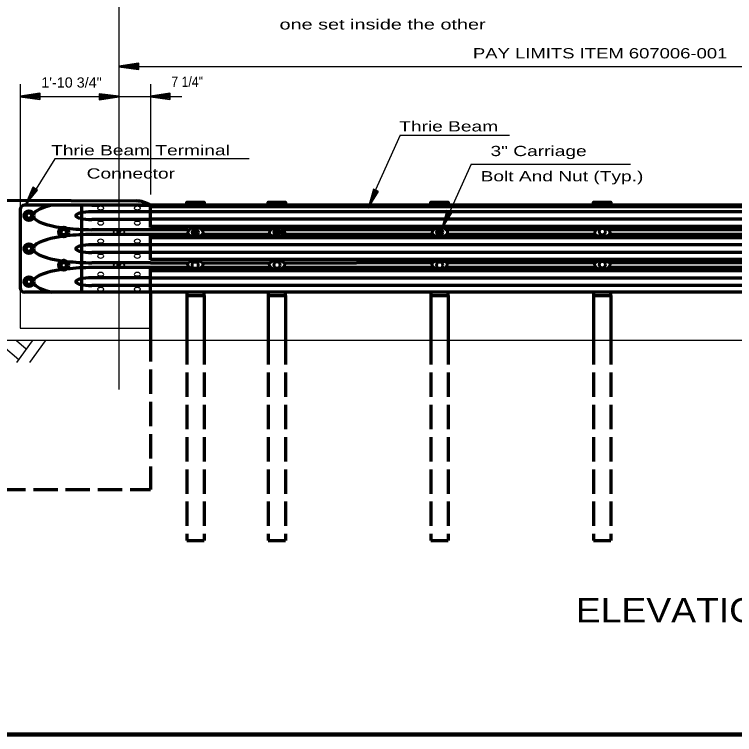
# Model space of a CAD drawing. Extents: x 856.9 to 891.7, y -2278.5 to -2254.7.
# Drawn here: x 863.91 to 872.97, y -2277.16 to -2268.1 of the extents above; entities that cross this region are included whole.
import ezdxf
from ezdxf.enums import TextEntityAlignment as Align

# ---------------------------------------------------------------- set-up
doc = ezdxf.new("R2010")
doc.units = 0
doc.header["$LTSCALE"] = 0.051
doc.header["$PDMODE"] = 32
doc.header["$PDSIZE"] = 0.0255
doc.linetypes.add('LONG_DASHED', pattern=[7.5, 6, -1.5])
doc.layers.add('1', color=7, linetype='Continuous', lineweight=70)
doc.layers.add('3', color=7, linetype='Continuous', lineweight=40)

msp = doc.modelspace()

# ---------------------------------------------------------------- linework, layer by layer
at = {"layer": '1', "lineweight": 25}
for p, q in [((865.22225, -2263.57275), (865.22225, -2272.82167)), ((865.22225, -2268.76158), (877.53042, -2268.76158)), ((863.98108, -2268.98175), (863.98108, -2270.37008)), ((865.61775, -2268.98175), (865.61775, -2270.37008)), ((868.75875, -2269.62258), (868.39367, -2270.431)), ((868.75925, -2269.62283), (870.134, -2269.62283)), ((864.41333, -2269.9225), (864.05383, -2270.50192)), ((866.86067, -2269.9225), (864.41333, -2269.9225)), ((869.651, -2269.98842), (869.28542, -2270.798)), ((869.651, -2269.98842), (871.65808, -2269.98842)), ((862.12625, -2272.20317), (882.07667, -2272.20317)), ((864.05633, -2272.31575), (863.93258, -2272.20975)), ((863.93525, -2272.48467), (864.133, -2272.20975)), ((864.09892, -2272.48467), (864.29667, -2272.20975)), ((863.96075, -2272.44933), (863.76567, -2272.28183))]:
    msp.add_line(p, q, dxfattribs=at)
at = {"layer": '1'}
for p, q in [((863.80467, -2270.44258), (865.43792, -2270.45175)), ((865.61775, -2270.5055), (864.03542, -2270.5055)), ((864.74875, -2270.50742), (864.74875, -2271.59408)), ((873.7235, -2270.5055), (865.61775, -2270.5055)), ((863.98108, -2270.5605), (863.98108, -2271.54242)), ((865.61775, -2270.58667), (864.881, -2270.58667)), ((865.61775, -2270.51925), (873.7235, -2270.51925)), ((873.7235, -2270.58867), (865.61775, -2270.58867)), ((865.61775, -2270.68367), (864.881, -2270.68367)), ((867.41158, -2270.68233), (865.61775, -2270.68233)), ((873.7235, -2270.68233), (867.41158, -2270.68233)), ((867.41158, -2270.77067), (865.61775, -2270.77067)), ((873.7235, -2270.77067), (867.41158, -2270.77067)), ((865.61775, -2270.81267), (864.881, -2270.81267)), ((865.61775, -2270.87425), (864.881, -2270.87425)), ((866.096, -2270.81267), (865.61775, -2270.81267)), ((866.09517, -2270.8735), (865.62342, -2270.8735)), ((867.129, -2270.81267), (866.27008, -2270.81267)), ((867.12075, -2270.8735), (866.27708, -2270.8735)), ((868.21067, -2270.81267), (867.29283, -2270.81267)), ((868.21067, -2270.8735), (867.29925, -2270.8735)), ((869.17425, -2270.81267), (868.21067, -2270.81267)), ((869.17425, -2270.8735), (868.21067, -2270.8735)), ((873.32717, -2270.81267), (871.38492, -2270.81267)), ((873.32717, -2270.8735), (871.38492, -2270.8735)), ((873.7235, -2270.91617), (865.61775, -2270.91617)), ((865.61775, -2271.00258), (864.881, -2271.00258)), ((873.7235, -2271.004), (865.61775, -2271.004)), ((865.61775, -2271.09958), (864.881, -2271.09958)), ((873.73325, -2271.09817), (865.61775, -2271.09817)), ((865.61775, -2271.22833), (864.881, -2271.22833)), ((873.7235, -2271.18667), (865.61775, -2271.18667)), ((865.61775, -2271.22833), (866.08875, -2271.22833)), ((866.27533, -2271.22833), (867.11167, -2271.22833)), ((867.30667, -2271.22833), (868.21067, -2271.22833)), ((869.17425, -2271.22833), (868.21067, -2271.22833)), ((873.32717, -2271.22833), (871.38492, -2271.22833)), ((865.61775, -2271.29017), (864.881, -2271.29017)), ((866.10483, -2271.29017), (865.61775, -2271.29017)), ((873.7235, -2271.33208), (865.61775, -2271.33208)), ((867.129, -2271.29017), (866.25733, -2271.29017)), ((868.37442, -2271.29017), (867.29283, -2271.29017)), ((869.17425, -2271.29017), (868.37442, -2271.29017)), ((873.32717, -2271.29017), (871.38492, -2271.29017)), ((865.61775, -2271.4185), (864.881, -2271.4185)), ((873.7235, -2271.42042), (865.61775, -2271.42042)), ((873.7235, -2271.51333), (865.61775, -2271.51333)), ((873.7235, -2271.59675), (864.03558, -2271.59675)), ((865.61775, -2271.51542), (864.881, -2271.51542)), ((865.61775, -2271.59675), (865.61775, -2272.20317)), ((866.07492, -2271.63858), (866.07492, -2272.20317)), ((866.29308, -2271.63858), (866.29308, -2272.20317)), ((867.09867, -2271.63858), (867.09867, -2272.20317)), ((867.31667, -2271.63858), (867.31667, -2272.20317)), ((869.14533, -2271.63858), (869.14533, -2272.20317)), ((869.36342, -2271.63858), (869.36342, -2272.20317)), ((871.19208, -2271.63858), (871.19208, -2272.20317)), ((871.41017, -2271.63858), (871.41017, -2272.20317))]:
    msp.add_line(p, q, dxfattribs=at)
at = {"layer": '1', "linetype": 'LONG_DASHED'}
for p, q in [((865.61775, -2271.59675), (865.61775, -2270.5055)), ((865.61775, -2272.16575), (865.61775, -2274.08083)), ((866.07492, -2272.20317), (866.07492, -2274.72208)), ((866.29308, -2272.20317), (866.29308, -2274.72208)), ((867.09867, -2272.20317), (867.09867, -2274.72208)), ((867.31667, -2272.20317), (867.31667, -2274.72208)), ((869.14533, -2272.20317), (869.14533, -2274.72208)), ((869.36342, -2272.20317), (869.36342, -2274.72208)), ((871.19208, -2272.20317), (871.19208, -2274.72208)), ((871.41017, -2272.20317), (871.41017, -2274.72208)), ((862.115, -2274.08083), (865.61775, -2274.08083)), ((866.07492, -2274.72208), (866.29308, -2274.72208)), ((867.09867, -2274.72208), (867.31667, -2274.72208)), ((869.14533, -2274.72208), (869.36342, -2274.72208)), ((871.19208, -2274.72208), (871.41017, -2274.72208))]:
    msp.add_line(p, q, dxfattribs=at)
at = {"layer": '1', "lineweight": 13}
for p, q in [((864.97667, -2270.51925), (864.881, -2270.51925)), ((865.61775, -2270.51925), (865.46775, -2270.51925)), ((867.189, -2270.81267), (867.187, -2270.81267)), ((865.61775, -2271.58283), (873.7235, -2271.58283))]:
    msp.add_line(p, q, dxfattribs=at)
at = {"layer": '1', "lineweight": 35}
for p, q in [((865.27008, -2270.8225), (865.17442, -2270.8225)), ((865.17442, -2270.86375), (865.27008, -2270.86375)), ((865.27008, -2271.239), (865.17442, -2271.239)), ((865.17442, -2271.27967), (865.27008, -2271.27967))]:
    msp.add_line(p, q, dxfattribs=at)
at = {"layer": '1', "lineweight": 40}
for points in [[(865.22225, -2268.76158), (865.46658, -2268.79308), (865.46658, -2268.72308)], [(863.98108, -2269.13825), (864.22542, -2269.16975), (864.22542, -2269.09975)], [(865.22225, -2269.13825), (864.978, -2269.10692), (864.978, -2269.177)], [(865.61775, -2269.13825), (865.86208, -2269.16975), (865.86208, -2269.09975)]]:
    msp.add_lwpolyline(points, close=True, dxfattribs=at)
for points in [[(865.46658, -2268.77542), (865.28317, -2268.76158), (865.46658, -2268.74067)], [(865.46658, -2268.767), (865.3795, -2268.75975), (865.46658, -2268.74925)], [(864.22542, -2269.15208), (864.042, -2269.13825), (864.22542, -2269.11733)], [(864.22542, -2269.14367), (864.13833, -2269.13642), (864.22542, -2269.12592)], [(864.978, -2269.12458), (865.16125, -2269.13825), (864.978, -2269.15925)], [(864.978, -2269.13308), (865.06508, -2269.14025), (864.978, -2269.15075)], [(865.86208, -2269.15208), (865.67867, -2269.13825), (865.86208, -2269.11733)], [(865.86208, -2269.14367), (865.775, -2269.13642), (865.86208, -2269.12592)]]:
    msp.add_lwpolyline(points, dxfattribs=at)
at = {"layer": '1', "lineweight": 25}
for points in [[(863.98108, -2269.13825), (865.22225, -2269.13825), (865.61775, -2269.13825), (866.01325, -2269.13825)], [(864.18333, -2270.30517), (864.0745, -2270.45375), (864.15383, -2270.28692)], [(864.17608, -2270.30075), (864.12375, -2270.37133), (864.16108, -2270.29142)], [(868.47042, -2270.32392), (868.382, -2270.48492), (868.43833, -2270.30942)], [(868.46242, -2270.31992), (868.42, -2270.39658), (868.44683, -2270.31267)], [(863.98108, -2270.37008), (863.98108, -2272.04983), (865.61775, -2272.04983)], [(869.39417, -2270.59508), (869.30575, -2270.75608), (869.36208, -2270.58058)], [(869.38617, -2270.59108), (869.34375, -2270.66775), (869.37058, -2270.58383)]]:
    msp.add_lwpolyline(points, dxfattribs=at)
for points in [[(864.0425, -2270.50567), (864.19833, -2270.31433), (864.13892, -2270.27767)], [(868.35708, -2270.54067), (868.48617, -2270.33108), (868.42258, -2270.30217)], [(869.28083, -2270.81183), (869.40992, -2270.60225), (869.34633, -2270.57333)]]:
    msp.add_lwpolyline(points, close=True, dxfattribs=at)
at = {"layer": '1'}
for points in [[(866.07492, -2270.50617), (866.07492, -2270.46475), (866.29308, -2270.46475), (866.29308, -2270.50617)], [(867.09867, -2270.50617), (867.09867, -2270.46475), (867.31667, -2270.46475), (867.31667, -2270.50617)], [(869.14533, -2270.50617), (869.14533, -2270.46475), (869.36342, -2270.46475), (869.36342, -2270.50617)], [(871.19208, -2270.50617), (871.19208, -2270.46475), (871.41017, -2270.46475), (871.41017, -2270.50617)], [(871.22117, -2270.81267), (870.42125, -2270.81267), (869.33808, -2270.81267)], [(871.22117, -2270.8735), (870.42125, -2270.8735), (869.33808, -2270.8735)], [(871.22117, -2271.22833), (870.42125, -2271.22833), (869.33808, -2271.22833)], [(871.22117, -2271.29017), (870.42125, -2271.29017), (869.33808, -2271.29017)], [(866.07492, -2271.59733), (866.07492, -2271.63858), (866.29308, -2271.63858), (866.29308, -2271.59733)], [(867.09867, -2271.59733), (867.09867, -2271.63858), (867.31667, -2271.63858), (867.31667, -2271.59733)], [(869.14533, -2271.59733), (869.14533, -2271.63858), (869.36342, -2271.63858), (869.36342, -2271.59733)], [(871.19208, -2271.59733), (871.19208, -2271.63858), (871.41017, -2271.63858), (871.41017, -2271.59733)]]:
    msp.add_lwpolyline(points, dxfattribs=at)
at = {"layer": '1', "lineweight": 13}
for points in [[(864.05442, -2270.65608), (864.0905, -2270.67642), (864.12575, -2270.65608), (864.12575, -2270.61492), (864.0905, -2270.59383), (864.05442, -2270.61492)], [(864.05442, -2271.072), (864.0905, -2271.09225), (864.12575, -2271.072), (864.12575, -2271.03067), (864.0905, -2271.00983), (864.05442, -2271.03067)]]:
    msp.add_lwpolyline(points, close=True, dxfattribs=at)
at = {"layer": '1'}
for points in [[(864.49075, -2270.86375), (864.52667, -2270.88458), (864.56267, -2270.86375), (864.56267, -2270.8225), (864.52667, -2270.80208), (864.49075, -2270.8225)], [(864.49075, -2271.27967), (864.52667, -2271.3005), (864.56267, -2271.27967), (864.56267, -2271.23833), (864.52667, -2271.21808), (864.49075, -2271.23833)], [(864.05442, -2271.488), (864.0905, -2271.50875), (864.12575, -2271.488), (864.12575, -2271.44667), (864.0905, -2271.42567), (864.05442, -2271.44667)]]:
    msp.add_lwpolyline(points, close=True, dxfattribs=at)
for centre, radius in [((864.09011, -2270.63517), 0.06135), ((864.09011, -2270.63517), 0.03579), ((864.52657, -2270.84317), 0.06135), ((864.52657, -2270.84317), 0.03579), ((864.09011, -2271.05117), 0.06135), ((864.09011, -2271.05117), 0.03579), ((864.52657, -2271.25917), 0.06135), ((864.52657, -2271.25917), 0.03579), ((864.09011, -2271.46717), 0.06135), ((864.09011, -2271.46717), 0.03579)]:
    msp.add_circle(centre, radius, dxfattribs=at)
at = {"layer": '1', "lineweight": 60}
for centre in [(866.18149, -2270.84498), (867.21093, -2270.84123), (869.25624, -2270.84315), (871.30292, -2270.83717), (866.18058, -2271.25917), (867.21093, -2271.25726), (869.25624, -2271.25917), (871.30292, -2271.25319)]:
    msp.add_circle(centre, 0.03923, dxfattribs=at)
at = {"layer": '1'}
for centre, radius, start, end in [((864.03556, -2270.56015), 0.05456, 90, 180), ((865.43793, -2270.77922), 0.32748, 56.69772, 90), ((864.03556, -2271.54218), 0.05456, 180, 270)]:
    msp.add_arc(centre, radius, start, end, dxfattribs=at)
at = {"layer": '1', "lineweight": 35}
for centre, start, end in [((865.17445, -2270.84319), 90, 270), ((865.26989, -2270.84319), 270, 90), ((865.17445, -2271.25919), 90, 270), ((865.26989, -2271.25919), 270, 90)]:
    msp.add_arc(centre, 0.02045, start, end, dxfattribs=at)
at = {"layer": '1'}
for centre, major_axis, ratio, start_param, end_param in [((864.8812, -2270.63525), (0.73653, 0), 0.24063, 2.3209747, 3.0378647), ((864.8812, -2270.63516), (-0.20151, 0), 0.24074, 4.712389, 7.8539816), ((864.8812, -2270.63525), (0.73653, 0), 0.24063, 3.2453343, 4.1709283), ((864.8812, -2270.63525), (0.73653, 0), 0.24063, 4.2686043, 4.712389), ((864.8812, -2271.05117), (-0.73653, 0), 0.240741, 4.712389, 5.1561874), ((864.8812, -2271.05117), (-0.73653, 0), 0.240741, 5.2538073, 6.1792823), ((864.8812, -2271.05116), (-0.20151, 0), 0.24074, 4.712389, 7.8539816), ((864.8812, -2271.05117), (-0.73653, 0), 0.240741, 0.1038925, 1.0293717), ((864.8812, -2271.05117), (-0.73653, 0), 0.240741, 1.1269942, 1.5707963), ((864.8812, -2271.46708), (-0.73653, 0), 0.24063, 5.2538543, 6.1790724), ((864.8812, -2271.46708), (-0.73653, 0), 0.24063, 4.712389, 5.15617), ((864.8812, -2271.467), (-0.20151, 0), 0.24074, 4.712389, 7.8539816), ((864.8812, -2271.46708), (-0.73653, 0), 0.24063, 0.1037239, 0.8206179)]:
    msp.add_ellipse(centre, major_axis=major_axis, ratio=ratio, start_param=start_param, end_param=end_param, dxfattribs=at)
at = {"layer": '1', "lineweight": 25}
for centre, major_axis, ratio in [((864.99031, -2270.54414), (-0.03919, 0), 0.679978), ((864.99031, -2270.54414), (0.03919, 0), 0.434256), ((865.45405, -2270.54414), (-0.03919, 0), 0.679978), ((865.45405, -2270.54414), (0.03919, 0), 0.434256), ((864.99031, -2270.7258), (-0.03919, 0), 0.442883), ((864.99031, -2270.7258), (0.03919, 0), 0.696674), ((865.45405, -2270.7258), (-0.03919, 0), 0.442883), ((865.45405, -2270.7258), (0.03919, 0), 0.696674), ((864.99031, -2270.96053), (-0.03919, 0), 0.679978), ((864.99031, -2270.96053), (0.03919, 0), 0.434256), ((865.45405, -2270.96053), (-0.03919, 0), 0.679978), ((865.45405, -2270.96053), (0.03919, 0), 0.434256), ((864.99031, -2271.1418), (-0.03919, 0), 0.442883), ((864.99031, -2271.1418), (0.03919, 0), 0.696674), ((865.45405, -2271.1418), (-0.03919, 0), 0.442883), ((865.45405, -2271.1418), (0.03919, 0), 0.696674), ((864.99031, -2271.37653), (-0.03919, 0), 0.679978), ((864.99031, -2271.37653), (0.03919, 0), 0.434256), ((865.45405, -2271.37653), (-0.03919, 0), 0.679978), ((865.45405, -2271.37653), (0.03919, 0), 0.434256), ((864.99031, -2271.55819), (-0.03919, 0), 0.442883), ((864.99031, -2271.55819), (0.03919, 0), 0.696674), ((865.45405, -2271.55819), (-0.03919, 0), 0.442883), ((865.45405, -2271.55819), (0.03919, 0), 0.696674)]:
    msp.add_ellipse(centre, major_axis=major_axis, ratio=ratio, start_param=3.1415927, end_param=6.2831853, dxfattribs=at)
at = {"layer": '1', "lineweight": 60}
for centre, major_axis, ratio, start_param, end_param in [((866.18466, -2270.85353), (0.09753, 0), 0.696674, 0, 3.1415927), ((867.21134, -2270.85353), (-0.09753, 0), 0.696674, 3.1415927, 6.2831853), ((869.25883, -2270.85353), (0.09753, 0), 0.696674, 0, 3.1415927), ((871.30351, -2270.85353), (-0.09753, 0), 0.696674, 3.1415927, 6.2831853), ((866.18466, -2270.85353), (-0.09753, 0), 0.442883, 0, 3.1415927), ((867.21134, -2270.85353), (0.09753, 0), 0.442883, 3.1415927, 6.2831853), ((869.25883, -2270.85353), (-0.09753, 0), 0.442883, 0, 3.1415927), ((871.30351, -2270.85353), (0.09753, 0), 0.442883, 3.1415927, 6.2831853), ((866.18349, -2271.24647), (-0.09753, 0), 0.442883, 3.1415927, 6.2831853), ((867.20917, -2271.24647), (0.09753, 0), 0.442883, 0, 3.1415927), ((869.25399, -2271.24647), (-0.09753, 0), 0.442883, 3.1415927, 6.2831853), ((871.30134, -2271.24647), (0.09753, 0), 0.442883, 0, 3.1415927), ((866.18349, -2271.24647), (0.09753, 0), 0.696674, 3.1415927, 6.2831853), ((867.20917, -2271.24647), (-0.09753, 0), 0.696674, 0, 3.1415927), ((869.25399, -2271.24647), (0.09753, 0), 0.696674, 3.1415927, 6.2831853), ((871.30134, -2271.24647), (-0.09753, 0), 0.696674, 0, 3.1415927)]:
    msp.add_ellipse(centre, major_axis=major_axis, ratio=ratio, start_param=start_param, end_param=end_param, dxfattribs=at)
at = {"layer": '1'}
for p in [(865.22225, -2270.8435), (866.16325, -2270.8735), (866.1815, -2270.84533), (867.187, -2270.8735), (867.21083, -2270.84158), (867.26883, -2270.8435), (869.25625, -2270.8435), (865.22225, -2271.25933)]:
    msp.add_point(p, dxfattribs=at)
at = {"layer": '3', "lineweight": 158}
msp.add_lwpolyline([(891.2, -2256.16333), (891.2, -2277.16333), (858.7, -2277.16333)], dxfattribs=at)

# ---------------------------------------------------------------- texts
at = {"layer": '1'}
for s, width, p in [('one set inside the other', 1.45, (867.24167, -2268.29417)), ('PAY LIMITS ITEM 607006-001', 1.35, (869.6745, -2268.658)), ('7 1/4"', 0.9, (865.88025, -2269.01592)), ('1\'-10 3/4"', 1.05, (864.24425, -2269.0255)), ('Thrie Beam', 1.4, (868.74683, -2269.57675)), ('Thrie Beam Terminal', 1.4, (864.36867, -2269.87767)), ('3" Carriage', 1.4, (869.89558, -2269.88692)), (' Connector', 1.4, (864.74867, -2270.16933)), ('Bolt And Nut (Typ.)', 1.4, (869.77083, -2270.2045))]:
    msp.add_text(s, height=0.1286, dxfattribs=dict(at, width=width)).set_placement(p)
at = {"layer": '1', "width": 1.15}
msp.add_text('ELEVATION', height=0.3052, dxfattribs=at).set_placement((872.28521, -2275.75083), align=Align.CENTER)

doc.saveas('drawing.dxf')
